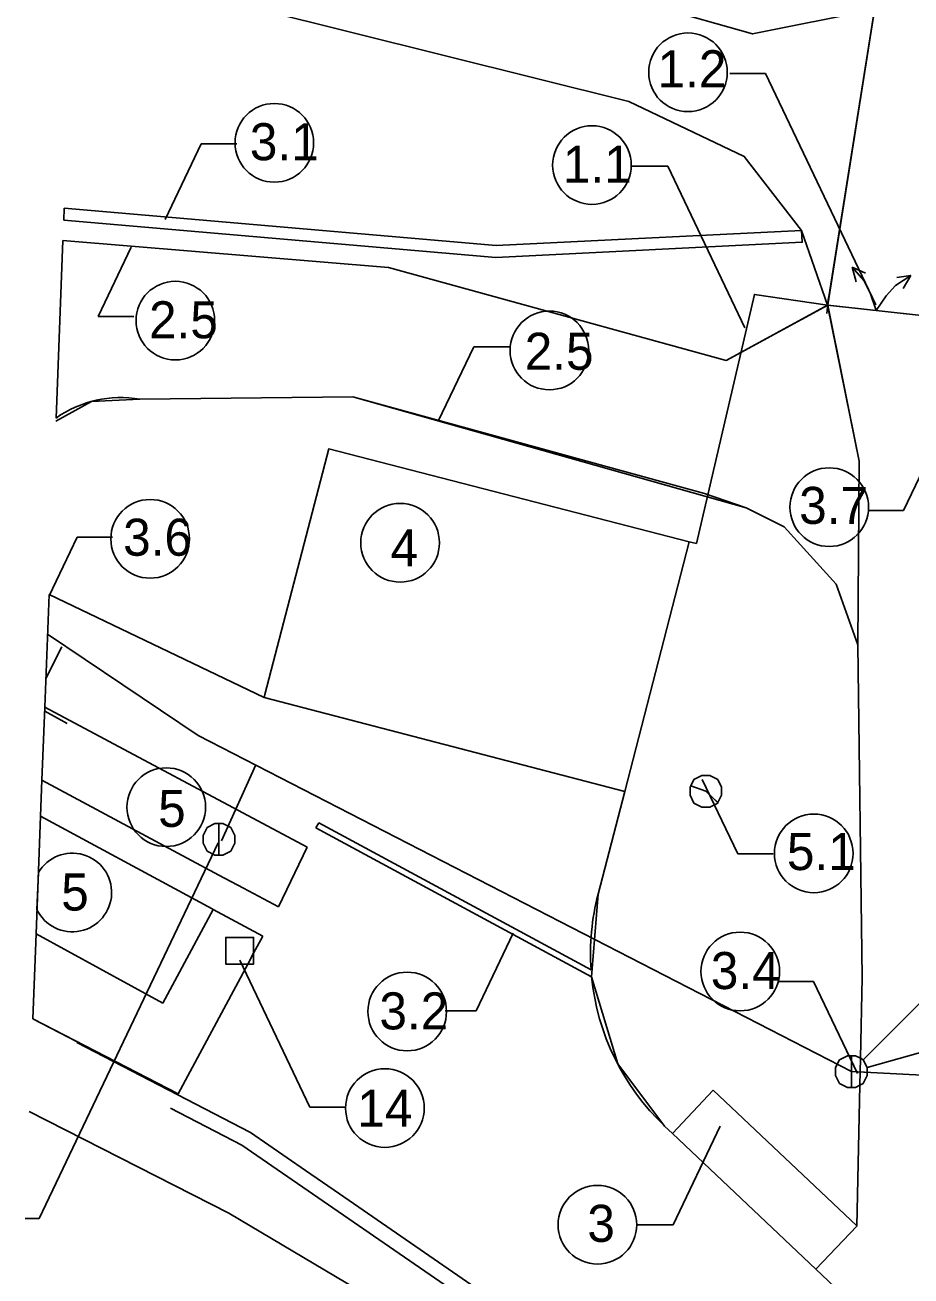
# Model space of a CAD drawing. Extents: x -438410 to -437811, y -1133174 to -1132817.
# Drawn here: x -438410.2 to -438365.3, y -1133117.4 to -1133054 of the extents above; entities that cross this region are included whole.
import ezdxf

# ---------------------------------------------------------------- set-up
doc = ezdxf.new("R2010")
doc.units = 0
for name, color, linetype in [('11 - bourané objekty', 7, 'Continuous'), ('12 - žlaby', 7, 'Continuous'), ('16 - betonové plochy', 7, 'Continuous'), ('17 - panel', 7, 'Continuous'), ('18 - asfalt', 7, 'Continuous'), ('19 - šotolina', 7, 'Continuous'), ('20 - popisy', 7, 'Continuous'), ('3 - ploty a brány', 7, 'Continuous'), ('4 - svodidla', 7, 'Continuous'), ('5 - obrubníky', 7, 'Continuous'), ('6 - kanalizace + šachty', 7, 'Continuous'), ('7 - elektro', 7, 'Continuous'), ('8 - liniové žlaby', 7, 'Continuous')]:
    doc.layers.add(name, color=color, linetype=linetype)

msp = doc.modelspace()

# ---------------------------------------------------------------- linework, layer by layer
at = {"layer": '11 - bourané objekty'}
for p, q in [((-438379.807, -1133092.848), (-438376.549, -1133080.2)), ((-438398.074, -1133088.086), (-438379.807, -1133092.848)), ((-438409.173, -1133088.575), (-438409.317, -1133092.269)), ((-438395.898, -1133095.665), (-438409.173, -1133088.575)), ((-438409.387, -1133094.086), (-438409.618, -1133100.05)), ((-438400.958, -1133094.665), (-438400.558, -1133094.465)), ((-438400.558, -1133094.465), (-438400.958, -1133094.665)), ((-438400.358, -1133094.465), (-438400.558, -1133094.465)), ((-438400.358, -1133096.065), (-438400.358, -1133094.465)), ((-438400.158, -1133094.465), (-438400.358, -1133094.465)), ((-438400.358, -1133094.465), (-438400.358, -1133096.065)), ((-438400.158, -1133094.465), (-438399.758, -1133094.665)), ((-438399.758, -1133094.665), (-438400.158, -1133094.465)), ((-438401.158, -1133095.065), (-438400.958, -1133094.665)), ((-438400.958, -1133094.665), (-438401.158, -1133095.065)), ((-438401.158, -1133095.465), (-438401.158, -1133095.065)), ((-438401.158, -1133095.065), (-438401.158, -1133095.465)), ((-438399.758, -1133094.665), (-438399.558, -1133095.065)), ((-438399.558, -1133095.065), (-438399.758, -1133094.665)), ((-438399.558, -1133095.065), (-438399.558, -1133095.465)), ((-438399.558, -1133095.465), (-438399.558, -1133095.065)), ((-438400.958, -1133095.865), (-438401.158, -1133095.465)), ((-438401.158, -1133095.465), (-438400.958, -1133095.865)), ((-438399.558, -1133095.465), (-438399.758, -1133095.865)), ((-438399.758, -1133095.865), (-438399.558, -1133095.465)), ((-438397.35, -1133098.689), (-438395.898, -1133095.665)), ((-438400.558, -1133096.065), (-438400.958, -1133095.865)), ((-438400.958, -1133095.865), (-438400.558, -1133096.065)), ((-438400.558, -1133096.065), (-438400.358, -1133096.065)), ((-438400.358, -1133096.065), (-438400.158, -1133096.065)), ((-438399.758, -1133095.865), (-438400.158, -1133096.065)), ((-438400.158, -1133096.065), (-438399.758, -1133095.865)), ((-438403.205, -1133103.555), (-438400.644, -1133098.816)), ((-438409.618, -1133100.05), (-438403.205, -1133103.555)), ((-438398.902, -1133101.581), (-438398.602, -1133101.022)), ((-438398.602, -1133101.022), (-438398.902, -1133101.581)), ((-438375.329, -1133107.96), (-438377.398, -1133110.148)), ((-438368.064, -1133114.829), (-438375.329, -1133107.96)), ((-438377.398, -1133110.148), (-438370.134, -1133117.016))]:
    msp.add_line(p, q, dxfattribs=at)
for points in [[(-438376.549, -1133080.2), (-438394.797, -1133075.5), (-438398.035, -1133087.936), (-438398.074, -1133088.086)], [(-438409.317, -1133092.269), (-438400.358, -1133097.075), (-438399.114, -1133097.742), (-438397.35, -1133098.689)], [(-438400.644, -1133098.81), (-438400.707, -1133098.776), (-438409.387, -1133094.086)], [(-438400.558, -1133094.465), (-438400.358, -1133094.465), (-438400.158, -1133094.465)], [(-438400.158, -1133096.065), (-438400.358, -1133096.065), (-438400.558, -1133096.065)], [(-438400.644, -1133098.816), (-438400.644, -1133098.811), (-438400.644, -1133098.81)], [(-438398.602, -1133101.022), (-438398.602, -1133100.226), (-438400.014, -1133100.226), (-438400.014, -1133101.581), (-438398.902, -1133101.581)], [(-438398.902, -1133101.581), (-438398.602, -1133101.581), (-438398.602, -1133101.022)], [(-438368.064, -1133114.833), (-438368.064, -1133114.831), (-438368.064, -1133114.829)], [(-438370.128, -1133117.016), (-438368.067, -1133114.836), (-438368.064, -1133114.833)], [(-438370.134, -1133117.016), (-438370.134, -1133117.016), (-438370.131, -1133117.016), (-438370.128, -1133117.016)]]:
    msp.add_lwpolyline(points, dxfattribs=at)
at = {"layer": '12 - žlaby'}
msp.add_line((-438408.194, -1133063.32), (-438408.218, -1133063.919), dxfattribs=at)
msp.add_lwpolyline([(-438408.218, -1133063.919), (-438386.337, -1133065.81), (-438370.825, -1133065.041), (-438370.855, -1133064.441), (-438386.326, -1133065.212), (-438408.194, -1133063.32)], dxfattribs=at)
at = {"layer": '16 - betonové plochy'}
for p, q in [((-438400.644, -1133098.816), (-438403.205, -1133103.555)), ((-438398.141, -1133100.162), (-438400.644, -1133098.816)), ((-438409.618, -1133100.05), (-438409.785, -1133104.352)), ((-438403.205, -1133103.555), (-438409.618, -1133100.05)), ((-438400.014, -1133101.581), (-438400.014, -1133100.226)), ((-438398.602, -1133101.022), (-438398.141, -1133100.162)), ((-438402.424, -1133108.146), (-438398.902, -1133101.581)), ((-438398.902, -1133101.581), (-438400.014, -1133101.581))]:
    msp.add_line(p, q, dxfattribs=at)
for points in [[(-438400.014, -1133100.226), (-438398.602, -1133100.226), (-438398.602, -1133101.022)], [(-438409.785, -1133104.352), (-438407.532, -1133105.513), (-438402.424, -1133108.146)]]:
    msp.add_lwpolyline(points, dxfattribs=at)
at = {"layer": '17 - panel'}
for p, q in [((-438367.682, -1133067.001), (-438368.292, -1133066.31)), ((-438368.292, -1133066.31), (-438368.092, -1133067.045)), ((-438368.092, -1133067.045), (-438368.292, -1133066.31)), ((-438368.292, -1133066.31), (-438367.626, -1133066.605)), ((-438367.626, -1133066.605), (-438368.292, -1133066.31)), ((-438368.292, -1133066.31), (-438367.682, -1133067.001)), ((-438367.369, -1133067.651), (-438367.682, -1133067.001)), ((-438367.682, -1133067.001), (-438367.369, -1133067.651)), ((-438366.577, -1133067.762), (-438366.098, -1133067.224)), ((-438366.098, -1133067.224), (-438366.577, -1133067.762)), ((-438366.098, -1133067.224), (-438365.321, -1133066.727)), ((-438365.321, -1133066.727), (-438366.098, -1133067.224)), ((-438365.321, -1133066.727), (-438366.042, -1133066.828)), ((-438366.042, -1133066.828), (-438365.321, -1133066.727)), ((-438365.321, -1133066.727), (-438365.715, -1133067.379)), ((-438365.715, -1133067.379), (-438365.321, -1133066.727)), ((-438367.085, -1133068.499), (-438367.369, -1133067.651)), ((-438367.369, -1133067.651), (-438367.085, -1133068.499)), ((-438366.577, -1133067.762), (-438367.085, -1133068.499)), ((-438367.085, -1133068.499), (-438366.577, -1133067.762)), ((-438367.085, -1133068.499), (-438369.536, -1133068.226)), ((-438369.536, -1133068.226), (-438367.938, -1133076.122)), ((-438369.534, -1133068.226), (-438367.085, -1133068.499)), ((-438367.085, -1133068.499), (-438364.634, -1133068.771)), ((-438367.085, -1133068.499), (-438367.085, -1133068.499)), ((-438367.085, -1133068.499), (-438367.085, -1133068.499)), ((-438364.633, -1133068.772), (-438367.085, -1133068.499)), ((-438367.938, -1133076.122), (-438368.008, -1133085.412)), ((-438368.008, -1133085.412), (-438367.791, -1133102.259)), ((-438367.791, -1133102.259), (-438367.881, -1133106.343)), ((-438367.881, -1133106.343), (-438367.731, -1133106.418)), ((-438367.731, -1133106.418), (-438367.531, -1133106.818)), ((-438367.531, -1133107.218), (-438367.731, -1133107.618)), ((-438367.531, -1133106.818), (-438367.531, -1133107.218)), ((-438367.911, -1133107.707), (-438368.067, -1133114.836)), ((-438367.731, -1133107.618), (-438367.911, -1133107.707)), ((-438368.067, -1133114.836), (-438370.134, -1133117.016)), ((-438370.134, -1133117.016), (-438362.747, -1133123.988))]:
    msp.add_line(p, q, dxfattribs=at)
for points in [[(-438367.16, -1133053.266), (-438367.164, -1133053.29), (-438369.534, -1133068.213)], [(-438369.534, -1133068.213), (-438369.534, -1133068.226), (-438369.534, -1133068.226)]]:
    msp.add_lwpolyline(points, dxfattribs=at)
at = {"layer": '18 - asfalt'}
for p, q in [((-438408.258, -1133064.95), (-438408.606, -1133073.941)), ((-438391.773, -1133066.319), (-438408.258, -1133064.95)), ((-438374.676, -1133071.022), (-438391.773, -1133066.319)), ((-438369.534, -1133068.226), (-438374.676, -1133071.022)), ((-438367.938, -1133076.122), (-438369.534, -1133068.226)), ((-438404.361, -1133072.992), (-438393.574, -1133072.866)), ((-438393.574, -1133072.866), (-438375.766, -1133077.768)), ((-438368.008, -1133085.412), (-438367.938, -1133076.122)), ((-438375.766, -1133077.768), (-438373.657, -1133078.485)), ((-438373.657, -1133078.485), (-438371.739, -1133079.443)), ((-438371.739, -1133079.443), (-438369.111, -1133082.341)), ((-438369.111, -1133082.341), (-438368.008, -1133085.412)), ((-438408.952, -1133082.868), (-438409.173, -1133088.575)), ((-438398.074, -1133088.086), (-438408.952, -1133082.868)), ((-438379.807, -1133092.848), (-438398.074, -1133088.086)), ((-438409.173, -1133088.575), (-438395.898, -1133095.665)), ((-438409.317, -1133092.269), (-438409.387, -1133094.086)), ((-438400.358, -1133097.075), (-438409.317, -1133092.269)), ((-438381.157, -1133098.038), (-438379.807, -1133092.848)), ((-438395.445, -1133094.687), (-438395.302, -1133094.423)), ((-438395.302, -1133094.423), (-438381.516, -1133101.874)), ((-438381.487, -1133102.231), (-438395.445, -1133094.687)), ((-438395.898, -1133095.665), (-438397.35, -1133098.689)), ((-438399.114, -1133097.742), (-438400.358, -1133097.075)), ((-438397.35, -1133098.689), (-438399.114, -1133097.742)), ((-438400.644, -1133098.816), (-438398.141, -1133100.162)), ((-438398.141, -1133100.162), (-438398.602, -1133101.022)), ((-438398.602, -1133101.022), (-438398.602, -1133101.581)), ((-438398.902, -1133101.581), (-438402.424, -1133108.146)), ((-438398.602, -1133101.581), (-438398.902, -1133101.581)), ((-438407.532, -1133105.513), (-438407.546, -1133105.544)), ((-438407.546, -1133105.544), (-438398.762, -1133110.111)), ((-438402.424, -1133108.146), (-438407.532, -1133105.513)), ((-438398.762, -1133110.111), (-438395.969, -1133112.033)), ((-438377.398, -1133110.148), (-438377.789, -1133109.778)), ((-438370.134, -1133117.016), (-438377.398, -1133110.148)), ((-438362.747, -1133123.988), (-438370.134, -1133117.016))]:
    msp.add_line(p, q, dxfattribs=at)
for points in [[(-438409.387, -1133094.086), (-438400.707, -1133098.776), (-438400.644, -1133098.816)], [(-438395.969, -1133112.033), (-438394.254, -1133113.214), (-438392.351, -1133114.523), (-438385.637, -1133119.145)]]:
    msp.add_lwpolyline(points, dxfattribs=at)
for centre, radius, start, end in [((-438405.342, -1133078.57), 5.663, 80.02217, 125.19251), ((-438369.544, -1133101.059), 12, 165.41646, 183.89281), ((-438369.544, -1133101.059), 12, 185.60348, 226.60123)]:
    msp.add_arc(centre, radius, start, end, dxfattribs=at)
at = {"layer": '19 - šotolina'}
msp.add_lwpolyline([(-438407.713, -1133050.896), (-438379.6, -1133057.917), (-438373.76, -1133060.703), (-438370.855, -1133064.441), (-438369.536, -1133068.226), (-438367.16, -1133053.265), (-438373.336, -1133054.497), (-438378.245, -1133053.104), (-438396.032, -1133049.116), (-438407.52, -1133045.926)], dxfattribs=at)
at = {"layer": '20 - popisy'}
for p, q in [((-438374.486, -1133056.498), (-438372.69, -1133056.498)), ((-438367.103, -1133068.209), (-438372.69, -1133056.498)), ((-438403.079, -1133063.892), (-438401.252, -1133060.063)), ((-438401.252, -1133060.063), (-438399.456, -1133060.063)), ((-438379.431, -1133061.188), (-438377.635, -1133061.188)), ((-438373.73, -1133069.373), (-438377.635, -1133061.188)), ((-438404.803, -1133065.3), (-438406.469, -1133068.793)), ((-438406.469, -1133068.793), (-438404.672, -1133068.793)), ((-438387.456, -1133070.331), (-438389.258, -1133074.107)), ((-438387.456, -1133070.331), (-438385.66, -1133070.331)), ((-438363.599, -1133074.235), (-438365.689, -1133078.618)), ((-438367.486, -1133078.618), (-438365.689, -1133078.618)), ((-438408.955, -1133082.948), (-438407.539, -1133079.978)), ((-438407.539, -1133079.978), (-438405.742, -1133079.978)), ((-438374.09, -1133095.991), (-438375.884, -1133092.228)), ((-438409.462, -1133114.448), (-438400.399, -1133095.449)), ((-438374.09, -1133095.991), (-438372.293, -1133095.991)), ((-438409.498, -1133096.946), (-438409.571, -1133098.825)), ((-438387.332, -1133103.951), (-438385.455, -1133100.016)), ((-438395.753, -1133108.819), (-438399.3, -1133101.383)), ((-438372.043, -1133102.462), (-438370.246, -1133102.462)), ((-438368.023, -1133107.123), (-438370.246, -1133102.462)), ((-438388.911, -1133103.951), (-438387.332, -1133103.951)), ((-438395.753, -1133108.819), (-438393.956, -1133108.819)), ((-438374.973, -1133109.789), (-438377.355, -1133114.78)), ((-438410.176, -1133114.448), (-438409.462, -1133114.448)), ((-438379.151, -1133114.78), (-438377.355, -1133114.78))]:
    msp.add_line(p, q, dxfattribs=at)
for centre in [(-438376.608, -1133056.442), (-438397.553, -1133060.012), (-438381.469, -1133061.137), (-438402.565, -1133069.01), (-438383.626, -1133070.519), (-438369.456, -1133078.451), (-438403.841, -1133080.056), (-438391.184, -1133080.254), (-438403.025, -1133093.636), (-438370.24, -1133095.975), (-438373.962, -1133101.954), (-438390.825, -1133103.978), (-438391.955, -1133108.865), (-438381.194, -1133114.771)]:
    msp.add_circle(centre, 1.991, dxfattribs=at)
msp.add_arc((-438407.781, -1133097.954), 1.991, 205.95586, 149.60375, dxfattribs=at)
at = {"layer": '3 - ploty a brány'}
for p, q in [((-438368.292, -1133066.31), (-438367.682, -1133067.001)), ((-438368.292, -1133066.31), (-438368.092, -1133067.045)), ((-438368.292, -1133066.31), (-438367.626, -1133066.605)), ((-438367.682, -1133067.001), (-438367.369, -1133067.651)), ((-438366.577, -1133067.762), (-438366.098, -1133067.224)), ((-438366.098, -1133067.224), (-438365.321, -1133066.727)), ((-438365.321, -1133066.727), (-438366.042, -1133066.828)), ((-438365.321, -1133066.727), (-438365.715, -1133067.379)), ((-438369.493, -1133067.834), (-438369.584, -1133068.656)), ((-438367.369, -1133067.651), (-438367.085, -1133068.499)), ((-438367.085, -1133068.499), (-438366.577, -1133067.762)), ((-438369.536, -1133068.226), (-438364.633, -1133068.772))]:
    msp.add_line(p, q, dxfattribs=at)
for points in [[(-438369.536, -1133068.226), (-438373.245, -1133067.682), (-438376.184, -1133080.286), (-438376.549, -1133080.2)], [(-438409.967, -1133109.048), (-438399.856, -1133114.179), (-438387.97, -1133121.246), (-438374.83, -1133130.419), (-438354.393, -1133143.331), (-438337.647, -1133153.525)]]:
    msp.add_lwpolyline(points, dxfattribs=at)
at = {"layer": '4 - svodidla'}
msp.add_line((-438408.035, -1133089.398), (-438409.181, -1133088.78), dxfattribs=at)
msp.add_lwpolyline([(-438402.81, -1133108.864), (-438399.193, -1133110.738), (-438386.079, -1133119.762), (-438379.059, -1133124.791), (-438365.024, -1133134.538), (-438341.279, -1133149.981)], dxfattribs=at)
at = {"layer": '5 - obrubníky'}
for points in [[(-438408.258, -1133064.95), (-438391.773, -1133066.319), (-438374.676, -1133071.022), (-438369.536, -1133068.226)], [(-438368.008, -1133085.412), (-438369.111, -1133082.341), (-438371.739, -1133079.443), (-438373.657, -1133078.485), (-438393.574, -1133072.866), (-438404.361, -1133072.992), (-438406.818, -1133073.108), (-438408.612, -1133074.098)], [(-438408.952, -1133082.868), (-438398.074, -1133088.086)], [(-438377.398, -1133110.148), (-438377.789, -1133109.778), (-438380.152, -1133106.633), (-438381.487, -1133102.231), (-438381.157, -1133098.038), (-438379.807, -1133092.848)], [(-438402.424, -1133108.146), (-438409.785, -1133104.352)]]:
    msp.add_lwpolyline(points, dxfattribs=at)
at = {"layer": '6 - kanalizace + šachty'}
for p, q in [((-438409.117, -1133087.122), (-438408.306, -1133085.528)), ((-438400.221, -1133095.344), (-438398.494, -1133091.496)), ((-438400.558, -1133094.465), (-438400.958, -1133094.665)), ((-438400.358, -1133094.465), (-438400.558, -1133094.465)), ((-438400.358, -1133096.065), (-438400.358, -1133094.465)), ((-438400.158, -1133094.465), (-438400.358, -1133094.465)), ((-438400.358, -1133094.465), (-438400.358, -1133096.065)), ((-438399.758, -1133094.665), (-438400.158, -1133094.465)), ((-438400.958, -1133094.665), (-438401.158, -1133095.065)), ((-438401.158, -1133095.065), (-438401.158, -1133095.465)), ((-438399.558, -1133095.065), (-438399.758, -1133094.665)), ((-438399.558, -1133095.465), (-438399.558, -1133095.065)), ((-438401.158, -1133095.465), (-438400.958, -1133095.865)), ((-438399.758, -1133095.865), (-438399.558, -1133095.465)), ((-438400.958, -1133095.865), (-438400.558, -1133096.065)), ((-438400.558, -1133096.065), (-438400.358, -1133096.065)), ((-438400.358, -1133096.065), (-438400.158, -1133096.065)), ((-438400.158, -1133096.065), (-438399.758, -1133095.865)), ((-438362.497, -1133101.181), (-438367.731, -1133106.418)), ((-438354.151, -1133103.018), (-438367.531, -1133106.818)), ((-438368.931, -1133106.418), (-438369.131, -1133106.818)), ((-438368.531, -1133106.218), (-438368.931, -1133106.418)), ((-438368.331, -1133106.218), (-438368.531, -1133106.218)), ((-438368.331, -1133107.818), (-438368.331, -1133106.218)), ((-438368.131, -1133106.218), (-438368.331, -1133106.218)), ((-438368.331, -1133106.218), (-438368.331, -1133107.818)), ((-438367.881, -1133106.343), (-438368.131, -1133106.218)), ((-438367.911, -1133107.707), (-438367.881, -1133106.343)), ((-438367.879, -1133106.344), (-438367.894, -1133107.04)), ((-438367.731, -1133106.418), (-438367.879, -1133106.344)), ((-438367.531, -1133106.818), (-438367.731, -1133106.418)), ((-438369.131, -1133106.818), (-438369.131, -1133107.218)), ((-438369.131, -1133107.218), (-438368.931, -1133107.618)), ((-438367.894, -1133107.04), (-438367.909, -1133107.706)), ((-438367.894, -1133107.04), (-438367.531, -1133107.059)), ((-438367.531, -1133107.059), (-438367.894, -1133107.04)), ((-438367.731, -1133107.618), (-438367.531, -1133107.218)), ((-438367.531, -1133107.059), (-438367.531, -1133106.818)), ((-438367.531, -1133107.218), (-438367.531, -1133107.059)), ((-438368.931, -1133107.618), (-438368.531, -1133107.818)), ((-438368.531, -1133107.818), (-438368.331, -1133107.818)), ((-438368.331, -1133107.818), (-438368.131, -1133107.818)), ((-438368.131, -1133107.818), (-438367.911, -1133107.707)), ((-438367.909, -1133107.706), (-438367.731, -1133107.618))]:
    msp.add_line(p, q, dxfattribs=at)
msp.add_lwpolyline([(-438335.271, -1133103.802), (-438341.325, -1133108.414), (-438368.331, -1133107.018), (-438401.416, -1133090.011), (-438401.416, -1133090.011), (-438409.03, -1133084.887)], dxfattribs=at)
at = {"layer": '7 - elektro'}
for p, q in [((-438375.905, -1133092.032), (-438376.305, -1133092.232)), ((-438375.105, -1133092.232), (-438375.505, -1133092.032)), ((-438376.466, -1133092.553), (-438376.505, -1133092.632)), ((-438376.505, -1133092.632), (-438376.505, -1133093.032)), ((-438376.305, -1133092.232), (-438376.466, -1133092.553)), ((-438375.705, -1133092.832), (-438376.466, -1133092.553)), ((-438376.466, -1133092.553), (-438375.705, -1133092.832)), ((-438374.905, -1133092.632), (-438375.105, -1133092.232)), ((-438374.905, -1133093.032), (-438374.905, -1133092.632)), ((-438376.505, -1133093.032), (-438376.305, -1133093.432)), ((-438375.096, -1133093.414), (-438375.705, -1133092.832)), ((-438375.705, -1133092.832), (-438375.089, -1133093.399)), ((-438375.089, -1133093.399), (-438374.905, -1133093.032)), ((-438376.305, -1133093.432), (-438375.905, -1133093.632)), ((-438375.905, -1133093.632), (-438375.505, -1133093.632)), ((-438375.505, -1133093.632), (-438375.105, -1133093.432)), ((-438375.105, -1133093.432), (-438375.096, -1133093.414))]:
    msp.add_line(p, q, dxfattribs=at)
msp.add_lwpolyline([(-438375.505, -1133092.032), (-438375.705, -1133092.032), (-438375.905, -1133092.032)], dxfattribs=at)
at = {"layer": '8 - liniové žlaby'}
msp.add_line((-438381.487, -1133102.231), (-438395.445, -1133094.687), dxfattribs=at)

# ---------------------------------------------------------------- texts
at = {"layer": '20 - popisy'}
for s, p in [('1.2', (-438378.149, -1133057.2)), ('3.1 ', (-438398.793, -1133060.891)), ('1.1', (-438382.939, -1133062.032)), ('2.5', (-438403.898, -1133069.905)), ('2.5', (-438384.875, -1133071.498)), ('3.7', (-438370.978, -1133079.299)), ('3.6', (-438405.208, -1133080.911)), ('4', (-438391.669, -1133081.443)), ('5', (-438403.435, -1133094.636)), ('5.1', (-438371.6, -1133096.82)), ('5', (-438408.344, -1133098.868)), ('3.4', (-438375.452, -1133102.843)), ('3.2', (-438392.232, -1133104.885)), ('14', (-438393.348, -1133109.812)), ('3', (-438381.704, -1133115.638))]:
    msp.add_text(s, height=1.875, dxfattribs=at).set_placement(p)

doc.saveas('drawing.dxf')
